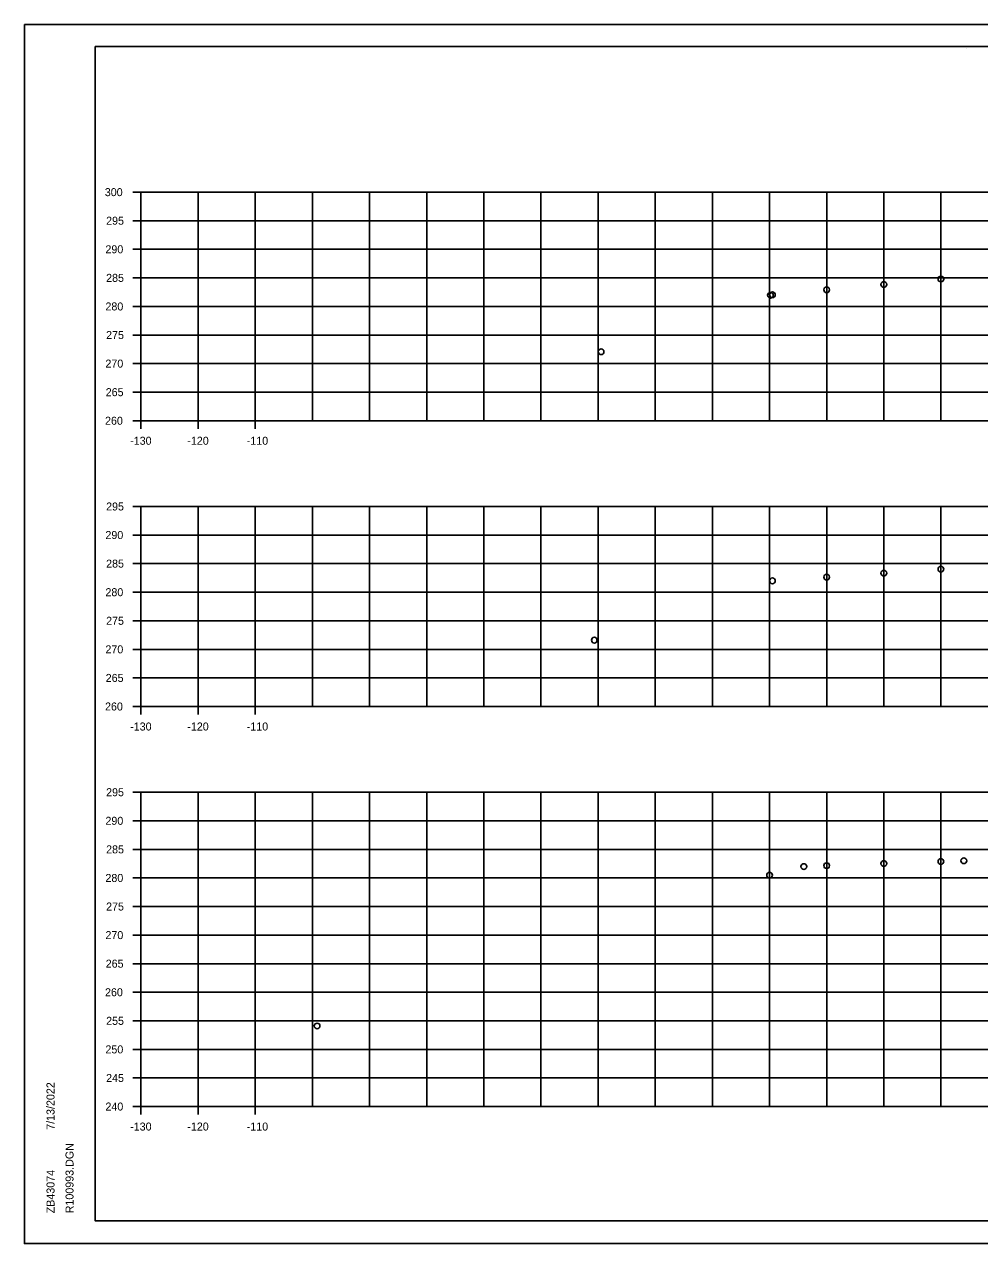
# Model space of a CAD drawing. Extents: x 4667 to 1632277, y -2100 to 724501.
# Drawn here: x 5969.1 to 6136.3, y -1110.4 to -897.1 of the extents above; entities that cross this region are included whole.
import ezdxf

# ---------------------------------------------------------------- set-up
doc = ezdxf.new("R2010")
doc.units = 0
for name, color, linetype in [('R_Axis', 7, 'Continuous'), ('R_Axis Annot', 7, 'Continuous'), ('R_Grid', 7, 'Continuous'), ('R_No Plot', 7, 'Continuous')]:
    doc.layers.add(name, color=color, linetype=linetype)

msp = doc.modelspace()

# ---------------------------------------------------------------- linework, layer by layer
at = {"layer": 'R_Axis'}
for p, q in [((5988.12, -926.43), (5989.52, -926.43)), ((5989.52, -966.43), (5989.52, -926.43)), ((5988.12, -931.43), (5989.52, -931.43)), ((5988.12, -936.43), (5989.52, -936.43)), ((5988.12, -941.43), (5989.52, -941.43)), ((5988.12, -946.43), (5989.52, -946.43)), ((5988.12, -951.43), (5989.52, -951.43)), ((5988.12, -956.43), (5989.52, -956.43)), ((5988.12, -961.43), (5989.52, -961.43)), ((5988.12, -966.43), (5989.52, -966.43)), ((5989.52, -967.83), (5989.52, -966.43)), ((5999.52, -967.83), (5999.52, -966.43)), ((6009.52, -967.83), (6009.52, -966.43)), ((5988.12, -981.43), (5989.52, -981.43)), ((5989.52, -1016.43), (5989.52, -981.43)), ((5988.12, -986.43), (5989.52, -986.43)), ((5988.12, -991.43), (5989.52, -991.43)), ((5988.12, -996.43), (5989.52, -996.43)), ((5988.12, -1001.43), (5989.52, -1001.43)), ((5988.12, -1006.43), (5989.52, -1006.43)), ((5988.12, -1011.43), (5989.52, -1011.43)), ((5988.12, -1016.43), (5989.52, -1016.43)), ((5989.52, -1017.83), (5989.52, -1016.43)), ((5999.52, -1017.83), (5999.52, -1016.43)), ((6009.52, -1017.83), (6009.52, -1016.43)), ((5988.12, -1031.43), (5989.52, -1031.43)), ((5989.52, -1086.43), (5989.52, -1031.43)), ((5988.12, -1036.43), (5989.52, -1036.43)), ((5988.12, -1041.43), (5989.52, -1041.43)), ((5988.12, -1046.43), (5989.52, -1046.43)), ((5988.12, -1051.43), (5989.52, -1051.43)), ((5988.12, -1056.43), (5989.52, -1056.43)), ((5988.12, -1061.43), (5989.52, -1061.43)), ((5988.12, -1066.43), (5989.52, -1066.43)), ((5988.12, -1071.43), (5989.52, -1071.43)), ((5988.12, -1076.43), (5989.52, -1076.43)), ((5988.12, -1081.43), (5989.52, -1081.43)), ((5988.12, -1086.43), (5989.52, -1086.43)), ((5989.52, -1087.83), (5989.52, -1086.43)), ((5999.52, -1087.83), (5999.52, -1086.43)), ((6009.52, -1087.83), (6009.52, -1086.43))]:
    msp.add_line(p, q, dxfattribs=at)
at = {"layer": 'R_Grid'}
for p, q in [((5989.52, -926.43), (6289.52, -926.43)), ((5989.52, -966.43), (5989.52, -926.43)), ((5999.52, -966.43), (5999.52, -926.43)), ((6009.52, -966.43), (6009.52, -926.43)), ((6019.52, -966.43), (6019.52, -926.43)), ((6029.52, -966.43), (6029.52, -926.43)), ((6039.52, -966.43), (6039.52, -926.43)), ((6049.52, -966.43), (6049.52, -926.43)), ((6059.52, -966.43), (6059.52, -926.43)), ((6069.52, -966.43), (6069.52, -926.43)), ((6079.52, -966.43), (6079.52, -926.43)), ((6089.52, -966.43), (6089.52, -926.43)), ((6099.52, -966.43), (6099.52, -926.43)), ((6109.52, -966.43), (6109.52, -926.43)), ((6119.52, -966.43), (6119.52, -926.43)), ((6129.52, -966.43), (6129.52, -926.43)), ((5989.52, -931.43), (6289.52, -931.43)), ((5989.52, -936.43), (6289.52, -936.43)), ((5989.52, -941.43), (6289.52, -941.43)), ((5989.52, -946.43), (6289.52, -946.43)), ((5989.52, -951.43), (6289.52, -951.43)), ((5989.52, -956.43), (6289.52, -956.43)), ((5989.52, -961.43), (6289.52, -961.43)), ((5989.52, -966.43), (6289.52, -966.43)), ((5989.52, -981.43), (6289.52, -981.43)), ((5989.52, -1016.43), (5989.52, -981.43)), ((5999.52, -1016.43), (5999.52, -981.43)), ((6009.52, -1016.43), (6009.52, -981.43)), ((6019.52, -1016.43), (6019.52, -981.43)), ((6029.52, -1016.43), (6029.52, -981.43)), ((6039.52, -1016.43), (6039.52, -981.43)), ((6049.52, -1016.43), (6049.52, -981.43)), ((6059.52, -1016.43), (6059.52, -981.43)), ((6069.52, -1016.43), (6069.52, -981.43)), ((6079.52, -1016.43), (6079.52, -981.43)), ((6089.52, -1016.43), (6089.52, -981.43)), ((6099.52, -1016.43), (6099.52, -981.43)), ((6109.52, -1016.43), (6109.52, -981.43)), ((6119.52, -1016.43), (6119.52, -981.43)), ((6129.52, -1016.43), (6129.52, -981.43)), ((5989.52, -986.43), (6289.52, -986.43)), ((5989.52, -991.43), (6289.52, -991.43)), ((5989.52, -996.43), (6289.52, -996.43)), ((5989.52, -1001.43), (6289.52, -1001.43)), ((5989.52, -1006.43), (6289.52, -1006.43)), ((5989.52, -1011.43), (6289.52, -1011.43)), ((5989.52, -1016.43), (6289.52, -1016.43)), ((5989.52, -1031.43), (6289.52, -1031.43)), ((5989.52, -1086.43), (5989.52, -1031.43)), ((5999.52, -1086.43), (5999.52, -1031.43)), ((6009.52, -1086.43), (6009.52, -1031.43)), ((6019.52, -1086.43), (6019.52, -1031.43)), ((6029.52, -1086.43), (6029.52, -1031.43)), ((6039.52, -1086.43), (6039.52, -1031.43)), ((6049.52, -1086.43), (6049.52, -1031.43)), ((6059.52, -1086.43), (6059.52, -1031.43)), ((6069.52, -1086.43), (6069.52, -1031.43)), ((6079.52, -1086.43), (6079.52, -1031.43)), ((6089.52, -1086.43), (6089.52, -1031.43)), ((6099.52, -1086.43), (6099.52, -1031.43)), ((6109.52, -1086.43), (6109.52, -1031.43)), ((6119.52, -1086.43), (6119.52, -1031.43)), ((6129.52, -1086.43), (6129.52, -1031.43)), ((5989.52, -1036.43), (6289.52, -1036.43)), ((5989.52, -1041.43), (6289.52, -1041.43)), ((5989.52, -1046.43), (6289.52, -1046.43)), ((5989.52, -1051.43), (6289.52, -1051.43)), ((5989.52, -1056.43), (6289.52, -1056.43)), ((5989.52, -1061.43), (6289.52, -1061.43)), ((5989.52, -1066.43), (6289.52, -1066.43)), ((5989.52, -1071.43), (6289.52, -1071.43)), ((5989.52, -1076.43), (6289.52, -1076.43)), ((5989.52, -1081.43), (6289.52, -1081.43)), ((5989.52, -1086.43), (6289.52, -1086.43))]:
    msp.add_line(p, q, dxfattribs=at)
at = {"layer": 'R_No Plot'}
for p, q in [((5969.12, -897.08), (6302.46, -897.08)), ((5981.52, -900.97), (6297.7, -900.97)), ((5981.52, -1106.43), (5981.52, -900.97)), ((6134.04, -901.23), (6134.04, -901.23)), ((6134.04, -901.23), (6134.04, -901.23)), ((5981.52, -1106.43), (5981.52, -1106.43)), ((6297.7, -1106.43), (5981.52, -1106.43)), ((5969.12, -1110.41), (6302.46, -1110.41))]:
    msp.add_line(p, q, dxfattribs=at)
for points in [[(5969.12, -897.08), (6302.46, -897.08), (6302.46, -1110.41), (5969.12, -1110.41)], [(6215.44, -900.97), (6215.44, -910.85), (6251.18, -910.85), (6251.18, -913.77), (6274.38, -913.77), (6274.38, -938.1), (6297.7, -938.1), (6297.7, -1106.43), (5981.52, -1106.43), (5981.52, -900.97)]]:
    msp.add_lwpolyline(points, close=True, dxfattribs=at)
for centre in [(6119.52, -942.57), (6129.52, -941.63), (6099.67, -944.48), (6100.02, -944.39), (6109.52, -943.5), (6070.05, -954.35), (6129.52, -992.4), (6100.02, -994.44), (6100.02, -994.44), (6109.52, -993.78), (6119.52, -993.09), (6068.86, -1004.82), (6129.52, -1043.56), (6133.52, -1043.42), (6105.52, -1044.44), (6109.52, -1044.28), (6119.52, -1043.92), (6099.52, -1045.94), (6020.35, -1072.33)]:
    msp.add_circle(centre, 0.5, dxfattribs=at)

# ---------------------------------------------------------------- texts
at = {"layer": 'R_Axis Annot'}
for s, p in [('300', (5983.19, -927.13)), ('295', (5983.42, -932.13)), ('290', (5983.3, -937.13)), ('285', (5983.42, -942.13)), ('280', (5983.3, -947.13)), ('275', (5983.42, -952.13)), ('270', (5983.3, -957.13)), ('265', (5983.35, -962.13)), ('260', (5983.23, -967.13)), ('-130', (5987.63, -970.63)), ('-120', (5997.63, -970.63)), ('-110', (6008.03, -970.63)), ('295', (5983.42, -982.13)), ('290', (5983.3, -987.13)), ('285', (5983.42, -992.13)), ('280', (5983.3, -997.13)), ('275', (5983.42, -1002.13)), ('270', (5983.3, -1007.13)), ('265', (5983.35, -1012.13)), ('260', (5983.23, -1017.13)), ('-130', (5987.63, -1020.63)), ('-120', (5997.63, -1020.63)), ('-110', (6008.03, -1020.63)), ('295', (5983.42, -1032.13)), ('290', (5983.3, -1037.13)), ('285', (5983.42, -1042.13)), ('280', (5983.3, -1047.13)), ('275', (5983.42, -1052.13)), ('270', (5983.3, -1057.13)), ('265', (5983.35, -1062.13)), ('260', (5983.23, -1067.13)), ('255', (5983.42, -1072.13)), ('250', (5983.3, -1077.13)), ('245', (5983.42, -1082.13)), ('240', (5983.3, -1087.13)), ('-130', (5987.63, -1090.63)), ('-120', (5997.63, -1090.63)), ('-110', (6008.03, -1090.63))]:
    msp.add_text(s, height=1.4, dxfattribs=at).set_placement(p)
at = {"layer": 'R_No Plot'}
for s, p in [('7/13/2022', (5974.39, -1090.5)), ('R100993.DGN', (5977.72, -1105.11)), ('ZB43074', (5974.39, -1105.11))]:
    msp.add_text(s, height=1.4, rotation=90, dxfattribs=at).set_placement(p)

doc.saveas('drawing.dxf')
